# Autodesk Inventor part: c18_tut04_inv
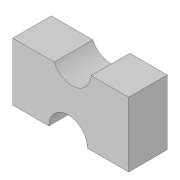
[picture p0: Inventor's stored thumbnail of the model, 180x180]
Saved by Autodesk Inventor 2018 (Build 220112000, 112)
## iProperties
Created: 2017-06
Part Number: c18_tut04_inv
Material: Generic
Document SubType Name: Modeling
Designer: CADCIM 00
Density: 1 g/cm^3
Appearance: Default
Author: CADCIM 00
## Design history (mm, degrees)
sketch "Sketch1"
  geometry: L1 (-60, 0)-(-60, 33.532); L2 (0, 30)-(0, 0); L3 (-60, 33.532)-(-40.6, 33.532); L4 (-21.474, 30)-(0, 30); L5 (0, 0)-(-18.704, 0); L6 (-38.704, 0)-(-60, 0); A1 r 10 centre (-30.614, 34.057) between (-40.6, 33.532) and (-21.474, 30); A2 r 10 centre (-28.704, 0) between (-18.704, 0) and (-38.704, 0)
  constraints: 12 end point, 5 parallel, 4 point on circle, 2 centre point, 2 horizontal, 2 perpendicular, 1 equal radius
  dimensions: "d0" = 60 distance between parallel lines of L1 L2 (= LEN); "d1" = 30 distance of L2.start L2.end (= WID); "d2" = 10 radius of A2 (= RAD)
extrude "Extrusion1" new body sketch "Sketch1" distance "d3" = 20 (= EXT); taper "d4" = 0 deg
body "Solid1"
other parameters: "LEN" = 60 [user parameter; used in 4 equation terms], "WID" = 30 (= 0.5 x LEN) [user parameter; used in 1 equation term], "RAD" = 10 (= 0.166667 x LEN) [user parameter; used in 1 equation term], "EXT" = 20 (= 0.333333 x LEN) [user parameter; used in 1 equation term]
